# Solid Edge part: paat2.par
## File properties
Author: Argo
Template: Normal.par
Last saved by: Argo
Revision: 15
Application: Solid Edge
Material: ABS Plastic, medium impact
Face Style: Black
Fill Style: ANSI34(Plastic)
Virtual Style: Black (Shiny)
Coef. of Thermal Exp: 5.8e-05
Thermal Conductivity: 2.0
Specific Heat: 0.0
Modulus of Elasticity: 2275269810.0
Poission's Ratio: 0.4
Yield Stress: 43436969.1
Ultimate Stress: 0.0
Elongation: 0.0
Density: 1024,000 kg/m^3
Accuracy: 0,990
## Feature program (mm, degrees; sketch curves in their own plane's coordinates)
make body feature "unnamed MakeBodyFeature 1"
body pattern "unnamed BodyPattern 1"
pattern "unnamed Pattern 1"
thinwall "Thinwall_2"  Thickness = 5 mm
web network "WebNetwork_5"  Profile_Plane1_Distance = 8 mm; Thickness = 1 mm
sketch for "unnamed Protrusion 1" plane through (-35.0993, 0, -15.9694) normal (-1, 0, 0) x-axis (0, -1, 0)
  line (-42.5, 26.9694) -> (42.5, 26.9694)
  line (42.5, 26.9694) -> (42.5, 23.9694)
  line (42.5, 23.9694) -> (0, 23.9694)
  line (0, 23.9694) -> (-42.5, 23.9694)
  line (-42.5, 23.9694) -> (-42.5, 26.9694)
extrude "unnamed Protrusion 1" add to key point along -normal
web network "WebNetwork_6"  Profile_Plane1_Distance = 2.6492 mm; Thickness = 0.25 mm
sketch for "unnamed Protrusion 2" plane through (159.1912, 0, -14.1181) normal (-1, 0, 0) x-axis (0, -1, 0)
  line (-40, 11.4689) -> (40, 11.4689)
  line (40, 14.4689) -> (40, 11.4689)
  line (-40, 14.4689) -> (40, 14.4689)
  line (-40, 11.4689) -> (-40, 14.4689)
extrude "unnamed Protrusion 2" add to key point along -normal
sketch for "unnamed Cutout 1" plane through (199.3162, 0, -1.1799) normal (1, 0, 0) x-axis (0, 0, -1)
  line (-46.0505, -25) -> (-46.0505, 25)
  line (-46.0505, 25) -> (-18.6111, 25)
  line (-18.6111, 25) -> (-18.6111, -25)
  line (-18.6111, -25) -> (-46.0505, -25)
extrude "unnamed Cutout 1" cut to key point along -normal
sketch for "unnamed Cutout 2" plane through (0.4034, 0, -11.9184) normal (1, 0, 0) x-axis (0, 1, 0)
  circle centre (0, 1.6073) radius 10
extrude "unnamed Cutout 2" cut to key point along -normal
sketch for "ExtrudedCutout_4" #1 plane through (0, 0, 28.8285) normal (0, 0, 1) x-axis (1, 0, 0)
  circle centre (30.6948, -63.9692) radius 1
sketch for "ExtrudedCutout_4" #2 plane through (0, 0, 28.8285) normal (0, 0, 1) x-axis (1, 0, 0)
  circle centre (45.6948, -63.9692) radius 1
sketch for "ExtrudedCutout_4" #3 plane through (0, 0, 28.8285) normal (0, 0, 1) x-axis (1, 0, 0)
  circle centre (45.6948, 63.9692) radius 1
sketch for "ExtrudedCutout_4" #4 plane through (0, 0, 28.8285) normal (0, 0, 1) x-axis (1, 0, 0)
  circle centre (30.6948, 63.9692) radius 1
extrude "ExtrudedCutout_4" cut finite 4 along -normal
sketch for "unnamed Cutout 3" #1 plane through (199.3162, 0, -1.1799) normal (1, 0, 0) x-axis (0, 1, 0)
  circle centre (-16, 9.8999) radius 1
sketch for "unnamed Cutout 3" #2 plane through (199.3162, 0, -1.1799) normal (1, 0, 0) x-axis (0, 1, 0)
  circle centre (-8, 9.8999) radius 1
sketch for "unnamed Cutout 3" #3 plane through (199.3162, 0, -1.1799) normal (1, 0, 0) x-axis (0, 1, 0)
  circle centre (8, 9.8999) radius 1
sketch for "unnamed Cutout 3" #4 plane through (199.3162, 0, -1.1799) normal (1, 0, 0) x-axis (0, 1, 0)
  circle centre (16, 9.8999) radius 1
extrude "unnamed Cutout 3" cut finite 5 along -normal
Other named dimensions: "ExtrudedSurface_3": FiniteDepth = 313.708 mm
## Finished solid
Body 1: solid body, 110 faces, 293 edges, 180 vertices, 4 internal voids.
  Faces by surface: offset 38, plane 33, spline 28, cylinder 10, swept 1
  Edges by curve: curve on surface 121, intersection 86, line 56, circle 22, spline 8
Body 2: solid body, 12 faces, 32 edges, 22 vertices.
  Faces by surface: spline 9, plane 2, swept 1
  Edges by curve: curve on surface 24, spline 4, line 3, circle 1
Body 3: sheet body, 1 face, 4 edges, 4 vertices.
  Faces by surface: swept 1
  Edges by curve: line 2, spline 2
Body 4: sheet body, 1 face, 4 edges, 4 vertices.
  Faces by surface: swept 1
  Edges by curve: line 2, spline 2
Bounding box of the edges (mm; curved faces can reach further): 399.572 x 313.708 x 304.189, from (-200, -156.854, -152.0947) to (199.5722, 156.854, 152.0947).
Cylindrical faces by radius (mm): R1 x8, R10 x2
Planar faces by outward normal: +x 5, +y 4, +z 13, -x 4, -y 3, -z 6
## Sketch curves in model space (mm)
circle centre (199.3162, -8, 8.72) radius 1
circle centre (199.3162, -16, 8.72) radius 1
circle centre (199.3162, 8, 8.72) radius 1
circle centre (199.3162, 16, 8.72) radius 1
circle centre (45.6948, -63.9692, 28.8285) radius 1
circle centre (30.6948, -63.9692, 28.8285) radius 1
circle centre (45.6948, 63.9692, 28.8285) radius 1
circle centre (30.6948, 63.9692, 28.8285) radius 1
circle centre (0.4034, 0, -10.3111) radius 10
circle centre (0.4034, 0, -10.3111) radius 10
line (199.3162, -25, 44.8706) -> (199.3162, 25, 44.8706)
line (199.3162, 25, 44.8706) -> (199.3162, 25, 17.4312)
line (199.3162, 25, 17.4312) -> (199.3162, -25, 17.4312)
line (199.3162, -25, 17.4312) -> (199.3162, -25, 44.8706)
line (159.1912, -40, 0.3508) -> (159.1912, -40, -2.6492)
line (159.1912, 40, 0.3508) -> (159.1912, -40, 0.3508)
line (159.1912, 40, -2.6492) -> (159.1912, 40, 0.3508)
line (159.1912, 40, -2.6492) -> (159.1912, -40, -2.6492)
line (-35.0993, 42.5, 8) -> (-35.0993, 42.5, 11)
line (-35.0993, 42.5, 11) -> (-35.0993, -42.5, 11)
line (-35.0993, -42.5, 11) -> (-35.0993, -42.5, 8)
line (-35.0993, -42.5, 8) -> (-35.0993, 0, 8)
line (-35.0993, 0, 8) -> (-35.0993, 42.5, 8)
spline (0, 0, -38.2053) -> (96.438, 0, -38.5756) -> (199.3162, 0, -34.791)
spline (-91.6762, 0, -34.7) -> (-45.3667, 0, -36.8662) -> (0, 0, -38.2053)
line (-91.6762, 0, 30.1829) -> (-91.6762, 0, -34.7)
spline (-200, 0, 38.0723) -> (-146.2954, 0, 32.5866) -> (-91.6762, 0, 30.1829)
spline (-200, 0, 38.0723) -> (-154.0283, 0, -11.9189) -> (-91.6762, 0, -34.7)
spline (-200, 0, 38.0723) -> (-14.6978, 0, -37.8425) -> (199.3162, 0, -34.791)
line (-91.6762, -60.6893, 30.1829) -> (-91.6762, -51.0291, 13.0087)
arc centre (-91.6762, 46.1668, 67.6799) radius 111.5167 from (-91.6762, -51.0291, 13.0087) through (-91.6762, -33.8618, -9.9822) to (-91.6762, -11.3963, -27.8317)
line (-91.6762, -11.3963, -27.8317) -> (-91.6762, 0, -34.7)
line (-91.6762, 0, -34.7) -> (-91.6762, 0, 30.1829)
line (-91.6762, 0, 30.1829) -> (-91.6762, -60.6893, 30.1829)
line (0, -67.0411, 28.8283) -> (0, -59.3178, -0.9828)
arc centre (0, -11.783, 11.3322) radius 49.1041 from (0, -59.3178, -0.9828) through (0, -42.499, -26.9789) to (0, -13.468, -37.7429)
line (0, -13.468, -37.7429) -> (0, 0, -38.2053)
line (0, 0, -38.2053) -> (0, 0, 28.8283)
line (0, 0, 28.8283) -> (0, -67.0411, 28.8283)
arc centre (199.3162, -40.1823, -18.9809) radius 15.2871 from (199.3162, -55.1536, -22.0723) through (199.3162, -49.5628, -31.0516) to (199.3162, -40.3808, -34.2668)
line (199.3162, -40.3808, -34.2668) -> (199.3162, 0, -34.791)
line (199.3162, 0, -34.791) -> (199.3162, 0, 32.4312)
line (199.3162, 0, 32.4312) -> (199.3162, -66.4076, 32.4312)
line (199.3162, -66.4076, 32.4312) -> (199.3162, -55.1536, -22.0723)
spline (-200, 0, 38.0723) -> (-2.2086, 0, 28.8338) -> (199.3162, 0, 32.4312)
spline (-200, 0, 0) -> (-8.7, -67.2067, 0) -> (199.5722, -66.4034, 0)
spline (-200, 0, 38.0723) -> (-2.2086, 0, 28.8338) -> (199.3162, 0, 32.4312)
spline (-200, 0, 38.0723) -> (-14.6978, 0, -37.8425) -> (199.3162, 0, -34.791)
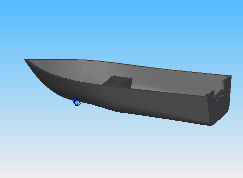
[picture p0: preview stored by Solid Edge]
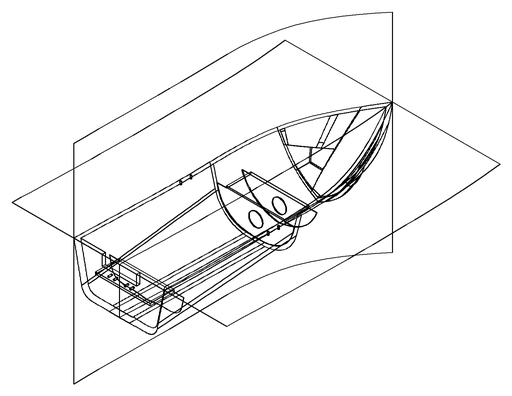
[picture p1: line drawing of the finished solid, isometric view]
